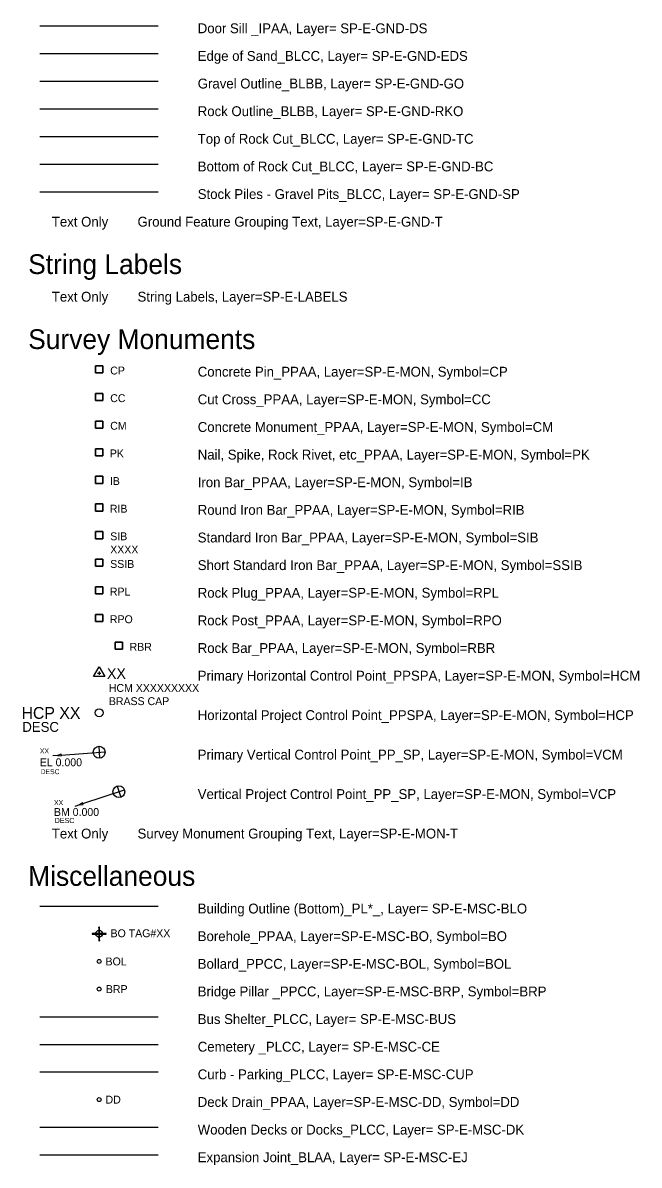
# Model space of a CAD drawing. Extents: x 500528 to 502626, y 4210261 to 4212624.
# Drawn here: x 501382.2 to 501538.5, y 4211737 to 4212026.4 of the extents above; entities that cross this region are included whole.
import ezdxf

# ---------------------------------------------------------------- set-up
doc = ezdxf.new("R2010")
doc.units = 0
for name, color, linetype in [('Default', 7, 'Continuous'), ('SP-E-GND-BC', 7, 'Continuous'), ('SP-E-GND-DS', 7, 'Continuous'), ('SP-E-GND-EDS', 7, 'Continuous'), ('SP-E-GND-GO', 7, 'Continuous'), ('SP-E-GND-RKO', 7, 'Continuous'), ('SP-E-GND-SP', 7, 'Continuous'), ('SP-E-GND-T', 7, 'Continuous'), ('SP-E-GND-TC', 7, 'Continuous'), ('SP-E-LABELS', 7, 'Continuous'), ('SP-E-MON', 7, 'Continuous'), ('SP-E-MON-T', 7, 'Continuous'), ('SP-E-MSC-BLO', 7, 'Continuous'), ('SP-E-MSC-BO', 7, 'Continuous'), ('SP-E-MSC-BOL', 7, 'Continuous'), ('SP-E-MSC-BRP', 7, 'Continuous'), ('SP-E-MSC-BUS', 7, 'Continuous'), ('SP-E-MSC-CE', 7, 'Continuous'), ('SP-E-MSC-CUP', 7, 'Continuous'), ('SP-E-MSC-DD', 7, 'Continuous'), ('SP-E-MSC-DK', 7, 'Continuous'), ('SP-E-MSC-EJ', 7, 'Continuous'), ('SP-E-MSC-T', 7, 'Continuous')]:
    doc.layers.add(name, color=color, linetype=linetype)

# ---------------------------------------------------------------- blocks, each defined once
blk = doc.blocks.new('CP')
at = {"layer": 'SP-E-MON'}
for points in [[(-0.09, 0.09), (0.09, 0.09), (0.09, -0.09), (-0.09, -0.09), (-0.09, 0.09)], [(0.09, -0.09), (0.09, 0.09), (-0.09, 0.09), (-0.09, -0.09), (0.09, -0.09)]]:
    blk.add_lwpolyline(points, dxfattribs=at)
at = {"layer": 'SP-E-MON-T'}
blk.add_text('CP', height=0.2, dxfattribs=at).set_placement((0.281, -0.13))
blk = doc.blocks.new('CC')
at = {"layer": 'SP-E-MON'}
for points in [[(-0.09, 0.09), (0.09, 0.09), (0.09, -0.09), (-0.09, -0.09), (-0.09, 0.09)], [(0.09, -0.09), (0.09, 0.09), (-0.09, 0.09), (-0.09, -0.09), (0.09, -0.09)]]:
    blk.add_lwpolyline(points, dxfattribs=at)
at = {"layer": 'SP-E-MON-T'}
blk.add_text('CC', height=0.2, dxfattribs=at).set_placement((0.281, -0.13))
blk = doc.blocks.new('CM')
at = {"layer": 'SP-E-MON'}
for points in [[(-0.09, 0.09), (0.09, 0.09), (0.09, -0.09), (-0.09, -0.09), (-0.09, 0.09)], [(0.09, -0.09), (0.09, 0.09), (-0.09, 0.09), (-0.09, -0.09), (0.09, -0.09)]]:
    blk.add_lwpolyline(points, dxfattribs=at)
at = {"layer": 'SP-E-MON-T'}
blk.add_text('CM', height=0.2, dxfattribs=at).set_placement((0.281, -0.13))
blk = doc.blocks.new('PK')
at = {"layer": 'SP-E-MON'}
for points in [[(-0.09, 0.09), (0.09, 0.09), (0.09, -0.09), (-0.09, -0.09), (-0.09, 0.09)], [(0.09, -0.09), (0.09, 0.09), (-0.09, 0.09), (-0.09, -0.09), (0.09, -0.09)]]:
    blk.add_lwpolyline(points, dxfattribs=at)
at = {"layer": 'SP-E-MON-T'}
blk.add_text('PK', height=0.2, dxfattribs=at).set_placement((0.272, -0.13))
blk = doc.blocks.new('IB')
at = {"layer": 'SP-E-MON'}
for points in [[(-0.09, 0.09), (0.09, 0.09), (0.09, -0.09), (-0.09, -0.09), (-0.09, 0.09)], [(0.09, -0.09), (0.09, 0.09), (-0.09, 0.09), (-0.09, -0.09), (0.09, -0.09)]]:
    blk.add_lwpolyline(points, dxfattribs=at)
at = {"layer": 'SP-E-MON-T'}
blk.add_text('IB', height=0.2, dxfattribs=at).set_placement((0.272, -0.13))
blk = doc.blocks.new('RIB')
at = {"layer": 'SP-E-MON'}
for points in [[(-0.09, 0.09), (0.09, 0.09), (0.09, -0.09), (-0.09, -0.09), (-0.09, 0.09)], [(0.09, -0.09), (0.09, 0.09), (-0.09, 0.09), (-0.09, -0.09), (0.09, -0.09)]]:
    blk.add_lwpolyline(points, dxfattribs=at)
at = {"layer": 'SP-E-MON-T'}
blk.add_text('RIB', height=0.2, dxfattribs=at).set_placement((0.272, -0.13))
blk = doc.blocks.new('SIB')
at = {"layer": 'SP-E-MON'}
for points in [[(-0.09, 0.09), (0.09, 0.09), (0.09, -0.09), (-0.09, -0.09), (-0.09, 0.09)], [(0.09, -0.09), (0.09, 0.09), (-0.09, 0.09), (-0.09, -0.09), (0.09, -0.09)]]:
    blk.add_lwpolyline(points, dxfattribs=at)
at = {"layer": 'SP-E-MON-T'}
for s, p in [('SIB', (0.281, -0.13)), ('XXXX', (0.281, -0.463))]:
    blk.add_text(s, height=0.2, dxfattribs=at).set_placement(p)
blk = doc.blocks.new('SSIB')
at = {"layer": 'SP-E-MON'}
for points in [[(-0.09, 0.09), (0.09, 0.09), (0.09, -0.09), (-0.09, -0.09), (-0.09, 0.09)], [(0.09, -0.09), (0.09, 0.09), (-0.09, 0.09), (-0.09, -0.09), (0.09, -0.09)]]:
    blk.add_lwpolyline(points, dxfattribs=at)
at = {"layer": 'SP-E-MON-T'}
blk.add_text('SSIB', height=0.2, dxfattribs=at).set_placement((0.281, -0.13))
blk = doc.blocks.new('RPL')
at = {"layer": 'SP-E-MON'}
for points in [[(-0.09, 0.09), (0.09, 0.09), (0.09, -0.09), (-0.09, -0.09), (-0.09, 0.09)], [(0.09, -0.09), (0.09, 0.09), (-0.09, 0.09), (-0.09, -0.09), (0.09, -0.09)]]:
    blk.add_lwpolyline(points, dxfattribs=at)
at = {"layer": 'SP-E-MON-T'}
blk.add_text('RPL', height=0.2, dxfattribs=at).set_placement((0.272, -0.13))
blk = doc.blocks.new('RPO')
at = {"layer": 'SP-E-MON'}
for points in [[(-0.09, 0.09), (0.09, 0.09), (0.09, -0.09), (-0.09, -0.09), (-0.09, 0.09)], [(0.09, -0.09), (0.09, 0.09), (-0.09, 0.09), (-0.09, -0.09), (0.09, -0.09)]]:
    blk.add_lwpolyline(points, dxfattribs=at)
at = {"layer": 'SP-E-MON-T'}
blk.add_text('RPO', height=0.2, dxfattribs=at).set_placement((0.272, -0.13))
blk = doc.blocks.new('RBR')
at = {"layer": 'SP-E-MON'}
for points in [[(-0.09, 0.09), (0.09, 0.09), (0.09, -0.09), (-0.09, -0.09), (-0.09, 0.09)], [(0.09, -0.09), (0.09, 0.09), (-0.09, 0.09), (-0.09, -0.09), (0.09, -0.09)]]:
    blk.add_lwpolyline(points, dxfattribs=at)
at = {"layer": 'SP-E-MON-T'}
blk.add_text('RBR', height=0.2, dxfattribs=at).set_placement((0.272, -0.13))
blk = doc.blocks.new('HCM')
at = {"layer": 'SP-E-MON'}
for points in [[(0, 0.167), (0.144, -0.083), (-0.144, -0.083), (0, 0.167)], [(0, 0.043), (0, -0.043)], [(-0.04, 0), (0.04, 0)]]:
    blk.add_lwpolyline(points, dxfattribs=at)
at = {"layer": 'SP-E-MON-T'}
for s, height, p in [('XX', 0.27, (0.197, -0.142)), ('HCM XXXXXXXXX', 0.2, (0.246, -0.472)), ('BRASS CAP', 0.2, (0.246, -0.806))]:
    blk.add_text(s, height=height, dxfattribs=at).set_placement(p)
blk = doc.blocks.new('HCP')
at = {"layer": 'SP-E-MON'}
blk.add_circle((0, 0), 0.1, dxfattribs=at)
blk.add_circle((0, 0), 0.1, dxfattribs=at)
at = {"layer": 'SP-E-MON-T'}
for s, height, p in [('HCP XX', 0.3, (-1.968, -0.154)), ('DESC', 0.25, (-1.948, -0.484))]:
    blk.add_text(s, height=height, dxfattribs=at).set_placement(p)
blk = doc.blocks.new('VCM')
at = {"layer": 'SP-E-MON'}
for points in [[(-0.96, -0.072), (0.15, 0.011)], [(-0.011, 0.15), (0.011, -0.15)], [(-1.052, -0.079), (-0.958, -0.095), (-0.961, -0.048), (-1.052, -0.079), (-1.177, -0.088)]]:
    blk.add_lwpolyline(points, dxfattribs=at)
blk.add_circle((0, 0), 0.15, dxfattribs=at)
at = {"layer": 'SP-E-MON-T'}
for s, height, p in [('XX', 0.125, (-1.502, -0.03)), ('EL 0.000', 0.2, (-1.505, -0.355)), ('DESC', 0.125, (-1.484, -0.555))]:
    blk.add_text(s, height=height, dxfattribs=at).set_placement(p)
blk = doc.blocks.new('VCP')
at = {"layer": 'SP-E-MON'}
for points in [[(-0.914, -0.302), (0.142, 0.047)], [(-0.047, 0.142), (0.047, -0.142)], [(-1.002, -0.331), (-0.906, -0.324), (-0.921, -0.28), (-1.002, -0.331), (-1.12, -0.371)]]:
    blk.add_lwpolyline(points, dxfattribs=at)
blk.add_circle((0, 0), 0.15, dxfattribs=at)
at = {"layer": 'SP-E-MON-T'}
for s, height, p in [('XX', 0.125, (-1.643, -0.339)), ('BM 0.000', 0.2, (-1.646, -0.614)), ('DESC', 0.13, (-1.626, -0.794))]:
    blk.add_text(s, height=height, dxfattribs=at).set_placement(p)
blk = doc.blocks.new('BO')
at = {"layer": 'SP-E-MSC-BO'}
for points in [[(0.174, 0.011), (-0.18, 0.011)], [(-0.18, 0.011), (-0.18, -0.011)], [(-0.087, 0.005), (-0.18, 0.011), (-0.18, 0.005), (-0.087, 0.005)], [(-0.087, 0.005), (-0.086, 0.011), (-0.18, 0.011), (-0.087, 0.005)], [(-0.087, 0), (-0.18, 0.005), (-0.18, 0), (-0.087, 0)], [(-0.087, 0), (-0.087, 0.005), (-0.18, 0.005), (-0.087, 0)], [(-0.087, -0.005), (-0.18, 0), (-0.18, -0.005), (-0.087, -0.005)], [(-0.087, -0.005), (-0.087, 0), (-0.18, 0), (-0.087, -0.005)], [(0.011, 0.166), (-0.011, 0.166)], [(-0.011, 0.166), (-0.011, -0.174)], [(0.011, 0.087), (-0.011, 0.166), (-0.011, 0.087), (0.011, 0.087)], [(0.011, 0.087), (0.011, 0.166), (-0.011, 0.166), (0.011, 0.087)], [(-0.011, 0.086), (0, 0.087), (-0.011, 0.087), (-0.011, 0.086)], [(0.011, 0.086), (0.011, 0.087), (0, 0.087), (0.011, 0.086)], [(0, 0), (0, 0)], [(0.011, -0.174), (0.011, 0.166)], [(0.174, 0.005), (0.086, 0.011), (0.087, 0.005), (0.174, 0.005)], [(0.174, 0.005), (0.174, 0.011), (0.086, 0.011), (0.174, 0.005)], [(0.174, 0), (0.087, 0.005), (0.087, 0), (0.174, 0)], [(0.174, 0), (0.174, 0.005), (0.087, 0.005), (0.174, 0)], [(0.174, -0.005), (0.087, 0), (0.087, -0.005), (0.174, -0.005)], [(0.174, -0.005), (0.174, 0), (0.087, 0), (0.174, -0.005)], [(0.174, -0.011), (0.174, 0.011)], [(-0.086, -0.011), (-0.18, -0.005), (-0.18, -0.011), (-0.086, -0.011)], [(-0.086, -0.011), (-0.087, -0.005), (-0.18, -0.005), (-0.086, -0.011)], [(-0.18, -0.011), (0.174, -0.011)], [(0, -0.087), (-0.011, -0.086), (-0.011, -0.087), (0, -0.087)], [(0.011, -0.174), (-0.011, -0.087), (-0.011, -0.174), (0.011, -0.174)], [(0.011, -0.174), (0.011, -0.087), (-0.011, -0.087), (0.011, -0.174)], [(-0.011, -0.174), (0.011, -0.174)], [(0.011, -0.087), (0.011, -0.086), (0, -0.087), (0.011, -0.087)], [(0.174, -0.011), (0.087, -0.005), (0.086, -0.011), (0.174, -0.011)], [(0.174, -0.011), (0.174, -0.005), (0.087, -0.005), (0.174, -0.011)]]:
    blk.add_lwpolyline(points, dxfattribs=at)
blk.add_circle((0, 0), 0.0871, dxfattribs=at)
at = {"layer": 'SP-E-MSC-T'}
blk.add_text('BO TAG#XX', height=0.2, dxfattribs=at).set_placement((0.289, -0.086))
blk = doc.blocks.new('BOL')
at = {"layer": 'SP-E-MSC-BOL'}
blk.add_lwpolyline([(0, 0), (0, 0)], dxfattribs=at)
blk.add_circle((0, 0), 0.05, dxfattribs=at)
at = {"layer": 'SP-E-MSC-T'}
blk.add_text('BOL', height=0.2, dxfattribs=at).set_placement((0.162, -0.1))
blk = doc.blocks.new('BRP')
at = {"layer": 'SP-E-MSC-BRP'}
blk.add_lwpolyline([(0, 0), (0, 0)], dxfattribs=at)
blk.add_circle((0, 0), 0.05, dxfattribs=at)
at = {"layer": 'SP-E-MSC-T'}
blk.add_text('BRP', height=0.2, dxfattribs=at).set_placement((0.171, -0.1))
blk = doc.blocks.new('DD')
at = {"layer": 'SP-E-MSC-DD'}
blk.add_lwpolyline([(0, 0), (0, 0)], dxfattribs=at)
blk.add_circle((0, 0), 0.05, dxfattribs=at)
at = {"layer": 'SP-E-MSC-T'}
blk.add_text('DD', height=0.2, dxfattribs=at).set_placement((0.162, -0.1))

msp = doc.modelspace()

# ---------------------------------------------------------------- linework, layer by layer
at = {"layer": 'SP-E-GND-BC'}
msp.add_line((501386.55, 4211990.59), (501416.55, 4211990.59), dxfattribs=at)
at = {"layer": 'SP-E-GND-DS'}
msp.add_line((501386.55, 4212025.59), (501416.55, 4212025.59), dxfattribs=at)
at = {"layer": 'SP-E-GND-EDS'}
msp.add_line((501386.55, 4212018.59), (501416.55, 4212018.59), dxfattribs=at)
at = {"layer": 'SP-E-GND-GO'}
msp.add_line((501386.55, 4212011.59), (501416.55, 4212011.59), dxfattribs=at)
at = {"layer": 'SP-E-GND-RKO'}
msp.add_line((501386.55, 4212004.59), (501416.55, 4212004.59), dxfattribs=at)
at = {"layer": 'SP-E-GND-SP'}
msp.add_line((501386.55, 4211983.59), (501416.55, 4211983.59), dxfattribs=at)
at = {"layer": 'SP-E-GND-TC'}
msp.add_line((501386.55, 4211997.59), (501416.55, 4211997.59), dxfattribs=at)
at = {"layer": 'SP-E-MSC-BLO'}
msp.add_line((501386.55, 4211802.59), (501416.55, 4211802.59), dxfattribs=at)
at = {"layer": 'SP-E-MSC-BUS'}
msp.add_line((501386.55, 4211774.59), (501416.55, 4211774.59), dxfattribs=at)
at = {"layer": 'SP-E-MSC-CE'}
msp.add_line((501386.55, 4211767.59), (501416.55, 4211767.59), dxfattribs=at)
at = {"layer": 'SP-E-MSC-CUP'}
msp.add_line((501386.55, 4211760.59), (501416.55, 4211760.59), dxfattribs=at)
at = {"layer": 'SP-E-MSC-DK'}
msp.add_line((501386.55, 4211746.59), (501416.55, 4211746.59), dxfattribs=at)
at = {"layer": 'SP-E-MSC-EJ'}
msp.add_line((501386.55, 4211739.59), (501416.55, 4211739.59), dxfattribs=at)

# ---------------------------------------------------------------- block references
at = {"layer": 'SP-E-MON', "xscale": 10, "yscale": 10}
for name, p in [('CP', (501401.55, 4211938.59)), ('CC', (501401.55, 4211931.59)), ('CM', (501401.55, 4211924.59)), ('PK', (501401.55, 4211917.59)), ('IB', (501401.55, 4211910.59)), ('RIB', (501401.55, 4211903.59)), ('SIB', (501401.55, 4211896.59)), ('SSIB', (501401.55, 4211889.59)), ('RPL', (501401.55, 4211882.59)), ('RPO', (501401.55, 4211875.59)), ('RBR', (501406.55, 4211868.59)), ('HCM', (501401.55, 4211861.59)), ('HCP', (501401.55, 4211851.59)), ('VCM', (501401.55, 4211841.59)), ('VCP', (501406.55, 4211831.59))]:
    msp.add_blockref(name, p, dxfattribs=at)
at = {"layer": 'SP-E-MSC-BO', "xscale": 10, "yscale": 10}
msp.add_blockref('BO', (501401.55, 4211795.59), dxfattribs=at)
at = {"layer": 'SP-E-MSC-BOL', "xscale": 10, "yscale": 10}
msp.add_blockref('BOL', (501401.55, 4211788.59), dxfattribs=at)
at = {"layer": 'SP-E-MSC-BRP', "xscale": 10, "yscale": 10}
msp.add_blockref('BRP', (501401.55, 4211781.59), dxfattribs=at)
at = {"layer": 'SP-E-MSC-DD', "xscale": 10, "yscale": 10}
msp.add_blockref('DD', (501401.55, 4211753.59), dxfattribs=at)

# ---------------------------------------------------------------- texts
at = {"layer": 'Default'}
for s, p in [('String Labels ', (501383.55, 4211962.74)), ('Survey Monuments ', (501383.55, 4211943.74)), ('Miscellaneous ', (501383.55, 4211807.74))]:
    msp.add_text(s, height=5, dxfattribs=at).set_placement(p)
at = {"layer": 'SP-E-GND-BC'}
msp.add_text('Bottom of Rock Cut_BLCC, Layer= SP-E-GND-BC ', height=2.5, dxfattribs=at).set_placement((501426.55, 4211988.74))
at = {"layer": 'SP-E-GND-DS'}
msp.add_text('Door Sill _IPAA, Layer= SP-E-GND-DS ', height=2.5, dxfattribs=at).set_placement((501426.55, 4212023.74))
at = {"layer": 'SP-E-GND-EDS'}
msp.add_text('Edge of Sand_BLCC, Layer= SP-E-GND-EDS ', height=2.5, dxfattribs=at).set_placement((501426.55, 4212016.74))
at = {"layer": 'SP-E-GND-GO'}
msp.add_text('Gravel Outline_BLBB, Layer= SP-E-GND-GO ', height=2.5, dxfattribs=at).set_placement((501426.55, 4212009.74))
at = {"layer": 'SP-E-GND-RKO'}
msp.add_text('Rock Outline_BLBB, Layer= SP-E-GND-RKO ', height=2.5, dxfattribs=at).set_placement((501426.55, 4212002.74))
at = {"layer": 'SP-E-GND-SP'}
msp.add_text('Stock Piles - Gravel Pits_BLCC, Layer= SP-E-GND-SP ', height=2.5, dxfattribs=at).set_placement((501426.55, 4211981.74))
at = {"layer": 'SP-E-GND-T'}
msp.add_text('Text Only        Ground Feature Grouping Text, Layer=SP-E-GND-T', height=2.5, dxfattribs=at).set_placement((501389.55, 4211974.74))
at = {"layer": 'SP-E-GND-TC'}
msp.add_text('Top of Rock Cut_BLCC, Layer= SP-E-GND-TC ', height=2.5, dxfattribs=at).set_placement((501426.55, 4211995.74))
at = {"layer": 'SP-E-LABELS'}
msp.add_text('Text Only        String Labels, Layer=SP-E-LABELS', height=2.5, dxfattribs=at).set_placement((501389.55, 4211955.74))
at = {"layer": 'SP-E-MON'}
for s, p in [('Concrete Pin_PPAA, Layer=SP-E-MON, Symbol=CP ', (501426.55, 4211936.74)), ('Cut Cross_PPAA, Layer=SP-E-MON, Symbol=CC ', (501426.55, 4211929.74)), ('Concrete Monument_PPAA, Layer=SP-E-MON, Symbol=CM ', (501426.55, 4211922.74)), ('Nail, Spike, Rock Rivet, etc_PPAA, Layer=SP-E-MON, Symbol=PK ', (501426.55, 4211915.74)), ('Iron Bar_PPAA, Layer=SP-E-MON, Symbol=IB ', (501426.55, 4211908.74)), ('Round Iron Bar_PPAA, Layer=SP-E-MON, Symbol=RIB ', (501426.55, 4211901.74)), ('Standard Iron Bar_PPAA, Layer=SP-E-MON, Symbol=SIB ', (501426.55, 4211894.74)), ('Short Standard Iron Bar_PPAA, Layer=SP-E-MON, Symbol=SSIB ', (501426.55, 4211887.74)), ('Rock Plug_PPAA, Layer=SP-E-MON, Symbol=RPL ', (501426.55, 4211880.74)), ('Rock Post_PPAA, Layer=SP-E-MON, Symbol=RPO ', (501426.55, 4211873.74)), ('Rock Bar_PPAA, Layer=SP-E-MON, Symbol=RBR ', (501426.55, 4211866.74)), ('Primary Horizontal Control Point_PPSPA, Layer=SP-E-MON, Symbol=HCM ', (501426.55, 4211859.74)), ('Horizontal Project Control Point_PPSPA, Layer=SP-E-MON, Symbol=HCP ', (501426.55, 4211849.74)), ('Primary Vertical Control Point_PP_SP, Layer=SP-E-MON, Symbol=VCM ', (501426.55, 4211839.74)), ('Vertical Project Control Point_PP_SP, Layer=SP-E-MON, Symbol=VCP ', (501426.55, 4211829.74))]:
    msp.add_text(s, height=2.5, dxfattribs=at).set_placement(p)
at = {"layer": 'SP-E-MON-T'}
msp.add_text('Text Only        Survey Monument Grouping Text, Layer=SP-E-MON-T', height=2.5, dxfattribs=at).set_placement((501389.55, 4211819.74))
at = {"layer": 'SP-E-MSC-BLO'}
msp.add_text('Building Outline (Bottom)_PL*_, Layer= SP-E-MSC-BLO ', height=2.5, dxfattribs=at).set_placement((501426.55, 4211800.74))
at = {"layer": 'SP-E-MSC-BO'}
msp.add_text('Borehole_PPAA, Layer=SP-E-MSC-BO, Symbol=BO ', height=2.5, dxfattribs=at).set_placement((501426.55, 4211793.74))
at = {"layer": 'SP-E-MSC-BOL'}
msp.add_text('Bollard_PPCC, Layer=SP-E-MSC-BOL, Symbol=BOL ', height=2.5, dxfattribs=at).set_placement((501426.55, 4211786.74))
at = {"layer": 'SP-E-MSC-BRP'}
msp.add_text('Bridge Pillar _PPCC, Layer=SP-E-MSC-BRP, Symbol=BRP ', height=2.5, dxfattribs=at).set_placement((501426.55, 4211779.74))
at = {"layer": 'SP-E-MSC-BUS'}
msp.add_text('Bus Shelter_PLCC, Layer= SP-E-MSC-BUS ', height=2.5, dxfattribs=at).set_placement((501426.55, 4211772.74))
at = {"layer": 'SP-E-MSC-CE'}
msp.add_text('Cemetery _PLCC, Layer= SP-E-MSC-CE ', height=2.5, dxfattribs=at).set_placement((501426.55, 4211765.74))
at = {"layer": 'SP-E-MSC-CUP'}
msp.add_text('Curb - Parking_PLCC, Layer= SP-E-MSC-CUP ', height=2.5, dxfattribs=at).set_placement((501426.55, 4211758.74))
at = {"layer": 'SP-E-MSC-DD'}
msp.add_text('Deck Drain_PPAA, Layer=SP-E-MSC-DD, Symbol=DD ', height=2.5, dxfattribs=at).set_placement((501426.55, 4211751.74))
at = {"layer": 'SP-E-MSC-DK'}
msp.add_text('Wooden Decks or Docks_PLCC, Layer= SP-E-MSC-DK ', height=2.5, dxfattribs=at).set_placement((501426.55, 4211744.74))
at = {"layer": 'SP-E-MSC-EJ'}
msp.add_text('Expansion Joint_BLAA, Layer= SP-E-MSC-EJ ', height=2.5, dxfattribs=at).set_placement((501426.55, 4211737.74))

doc.saveas('drawing.dxf')
